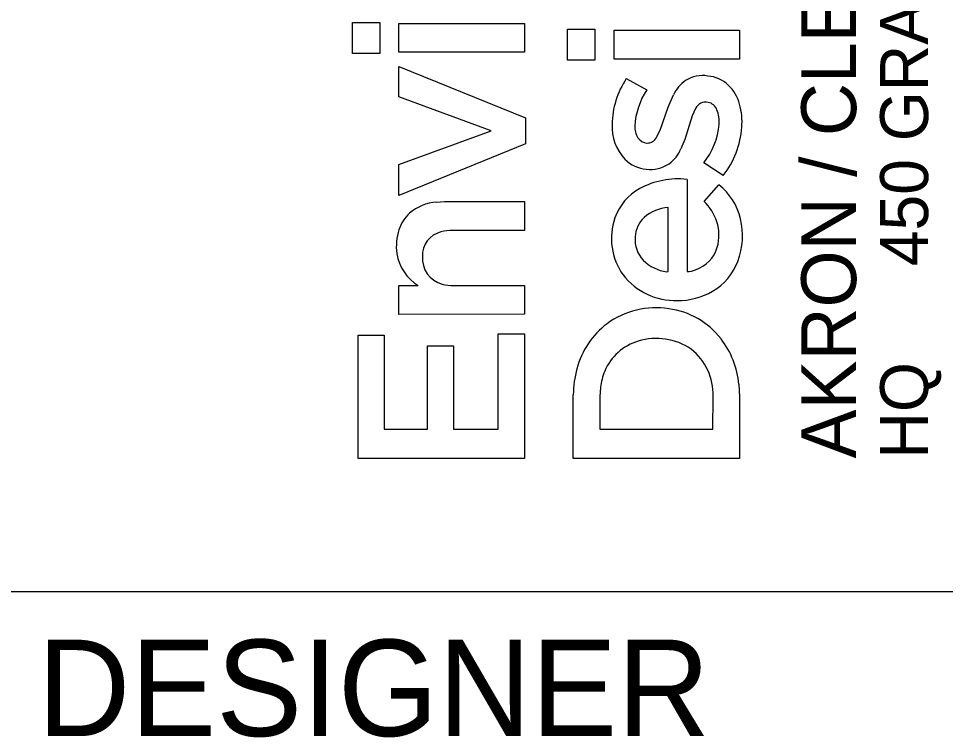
# Model space of a CAD drawing. Extents: x 0 to 34, y 0 to 22.
# Drawn here: x 32.03 to 32.993, y 2.849 to 3.594 of the extents above; entities that cross this region are included whole.
import ezdxf

# ---------------------------------------------------------------- set-up
doc = ezdxf.new("R2010")
doc.units = 0
doc.layers.add('SH_Border', color=7, linetype='Continuous')
doc.layers.add('SH_Data', color=7, linetype='Continuous')

msp = doc.modelspace()

# ---------------------------------------------------------------- linework, layer by layer
at = {"layer": 'SH_Border'}
msp.add_line((32, 3), (33.5, 3), dxfattribs=at)
at = {"layer": 'SH_Data'}
for p, q in [((32.37705, 3.55818), (32.37705, 3.59026)), ((32.37705, 3.59026), (32.40543, 3.59026)), ((32.40543, 3.59026), (32.40543, 3.55818)), ((32.42542, 3.55942), (32.42542, 3.58928)), ((32.42542, 3.58928), (32.55571, 3.58928)), ((32.55571, 3.58928), (32.55571, 3.55942)), ((32.60051, 3.55111), (32.60051, 3.58319)), ((32.60051, 3.58319), (32.62889, 3.58319)), ((32.62889, 3.58319), (32.62889, 3.55111)), ((32.64888, 3.55234), (32.64888, 3.5822)), ((32.64888, 3.5822), (32.77917, 3.5822)), ((32.77917, 3.5822), (32.77917, 3.55234)), ((32.40543, 3.55818), (32.37705, 3.55818)), ((32.55571, 3.55942), (32.42542, 3.55942)), ((32.77917, 3.55234), (32.64888, 3.55234)), ((32.42542, 3.51327), (32.42542, 3.5446)), ((32.42542, 3.5446), (32.5567, 3.4913)), ((32.62889, 3.55111), (32.60051, 3.55111)), ((32.66151, 3.53207), (32.68268, 3.52025)), ((32.52117, 3.47798), (32.42542, 3.51327)), ((32.70483, 3.50258), (32.71036, 3.51526)), ((32.69675, 3.47868), (32.70483, 3.50258)), ((32.73342, 3.50101), (32.72985, 3.4933)), ((32.5567, 3.4913), (32.5567, 3.46441)), ((32.72985, 3.4933), (32.72213, 3.46882)), ((32.42542, 3.44294), (32.52117, 3.47798)), ((32.69299, 3.47117), (32.69675, 3.47868)), ((32.72213, 3.46882), (32.71822, 3.45921)), ((32.5567, 3.46441), (32.42542, 3.41086)), ((32.42542, 3.41086), (32.42542, 3.44294)), ((32.76214, 3.43141), (32.74198, 3.44469)), ((32.72453, 3.42747), (32.72463, 3.33195)), ((32.74228, 3.40465), (32.75768, 3.422)), ((32.46439, 3.40397), (32.47289, 3.40443)), ((32.47289, 3.40443), (32.55571, 3.40443)), ((32.55571, 3.40443), (32.55571, 3.37465)), ((32.70489, 3.33182), (32.70489, 3.39834)), ((32.55571, 3.37465), (32.4814, 3.37457)), ((32.70361, 3.33165), (32.70489, 3.33182)), ((32.42542, 3.31728), (32.44552, 3.31733)), ((32.42542, 3.28747), (32.42542, 3.31728)), ((32.48222, 3.31733), (32.55569, 3.31733)), ((32.55569, 3.31733), (32.55571, 3.28756)), ((32.55571, 3.28756), (32.42542, 3.28747)), ((32.38298, 3.13791), (32.38298, 3.26598)), ((32.38298, 3.26598), (32.41012, 3.26598)), ((32.41012, 3.26598), (32.41012, 3.16827)), ((32.52857, 3.16827), (32.52857, 3.26722)), ((32.52857, 3.26722), (32.55571, 3.26722)), ((32.55571, 3.26722), (32.55571, 3.13791)), ((32.45503, 3.16827), (32.45503, 3.25488)), ((32.45503, 3.25488), (32.48218, 3.25488)), ((32.48218, 3.25488), (32.48218, 3.16827)), ((32.77847, 3.21497), (32.77917, 3.2021)), ((32.63465, 3.21178), (32.63407, 3.2023)), ((32.60643, 3.13799), (32.60644, 3.204)), ((32.63407, 3.2023), (32.63407, 3.16838)), ((32.75149, 3.16834), (32.75153, 3.20239)), ((32.77917, 3.2021), (32.77917, 3.138)), ((32.41012, 3.16827), (32.45503, 3.16827)), ((32.48218, 3.16827), (32.52857, 3.16827)), ((32.63407, 3.16838), (32.75149, 3.16834)), ((32.55571, 3.13791), (32.38298, 3.13791)), ((32.77917, 3.138), (32.60643, 3.13799))]:
    msp.add_line(p, q, dxfattribs=at)
for points in [[(32.37705, 3.55818), (32.37705, 3.59026), (32.40543, 3.59026), (32.40543, 3.55818)], [(32.42542, 3.55942), (32.42542, 3.58928), (32.55571, 3.58928), (32.55571, 3.55942)], [(32.60051, 3.55111), (32.60051, 3.58319), (32.62889, 3.58319), (32.62889, 3.55111)], [(32.64888, 3.55234), (32.64888, 3.5822), (32.77917, 3.5822), (32.77917, 3.55234)], [(32.42542, 3.41086), (32.42542, 3.44294), (32.52117, 3.47798), (32.42542, 3.51327), (32.42542, 3.5446), (32.5567, 3.4913), (32.5567, 3.46441)], [(32.38298, 3.13791), (32.38298, 3.26598), (32.41012, 3.26598), (32.41012, 3.16827), (32.45503, 3.16827), (32.45503, 3.25488), (32.48218, 3.25488), (32.48218, 3.16827), (32.52857, 3.16827), (32.52857, 3.26722), (32.55571, 3.26722), (32.55571, 3.13791)]]:
    msp.add_lwpolyline(points, close=True, dxfattribs=at)
for points in [[(32.66151, 3.53207), (32.68268, 3.52025)], [(32.69299, 3.47117), (32.69675, 3.47868), (32.70483, 3.50258), (32.71036, 3.51526)], [(32.73342, 3.50101), (32.72985, 3.4933), (32.72213, 3.46882), (32.71822, 3.45921)], [(32.76214, 3.43141), (32.74198, 3.44469)], [(32.72453, 3.42747), (32.72463, 3.33195)], [(32.74228, 3.40465), (32.75768, 3.422)], [(32.46439, 3.40397), (32.47289, 3.40443), (32.55571, 3.40443), (32.55571, 3.37465), (32.4814, 3.37457)], [(32.70361, 3.33165), (32.70489, 3.33182), (32.70489, 3.39834)], [(32.42542, 3.28747), (32.42542, 3.31728), (32.44552, 3.31733)], [(32.48222, 3.31733), (32.55569, 3.31733), (32.55571, 3.28756), (32.42542, 3.28747)], [(32.77847, 3.21497), (32.77917, 3.2021), (32.77917, 3.138), (32.60643, 3.13799)], [(32.63465, 3.21178), (32.63407, 3.2023), (32.63407, 3.16838), (32.75149, 3.16834), (32.75153, 3.20239)], [(32.60643, 3.13799), (32.60644, 3.204)]]:
    msp.add_lwpolyline(points, dxfattribs=at)
for centre, radius, start, end in [((32.73636, 3.48258), 0.08973, 146.53104, 178.7571), ((32.73636, 3.48258), 0.08973, 146.53104, 178.7571), ((32.7406, 3.5026), 0.03263, 80.17192, 122.51969), ((32.7406, 3.5026), 0.03263, 80.17192, 122.51969), ((32.74278, 3.49824), 0.03667, 47.79344, 84.68918), ((32.74278, 3.49824), 0.03667, 47.79344, 84.68918), ((32.74661, 3.49713), 0.04053, 125.51182, 153.41595), ((32.74661, 3.49713), 0.04053, 125.51182, 153.41595), ((32.73788, 3.4946), 0.04267, 14.9966, 46.20632), ((32.73788, 3.4946), 0.04267, 14.9966, 46.20632), ((32.74519, 3.4789), 0.07495, 146.51121, 176.91007), ((32.74519, 3.4789), 0.07495, 146.51121, 176.91007), ((32.74384, 3.49631), 0.01143, 76.66094, 155.7053), ((32.74384, 3.49631), 0.01143, 76.66094, 155.7053), ((32.74397, 3.49511), 0.01256, 21.5098, 78.52618), ((32.74397, 3.49511), 0.01256, 21.5098, 78.52618), ((32.71044, 3.48674), 0.07121, 355.83062, 15.39138), ((32.71044, 3.48674), 0.07121, 355.83062, 15.39138), ((32.72592, 3.48766), 0.03209, 354.57264, 22.06805), ((32.72592, 3.48766), 0.03209, 354.57264, 22.06805), ((32.69666, 3.48238), 0.05005, 177.53659, 222.79318), ((32.69666, 3.48238), 0.05005, 177.53659, 222.79318), ((32.68248, 3.49149), 0.0757, 321.81101, 354.79685), ((32.68248, 3.49149), 0.0757, 321.81101, 354.79685), ((32.6931, 3.48233), 0.02276, 178.47474, 211.08679), ((32.6931, 3.48233), 0.02276, 178.47474, 211.08679), ((32.68952, 3.4882), 0.09219, 321.9777, 355.87384), ((32.68952, 3.4882), 0.09219, 321.9777, 355.87384), ((32.68331, 3.4767), 0.01148, 212.23676, 268.37769), ((32.68331, 3.4767), 0.01148, 212.23676, 268.37769), ((32.68342, 3.47589), 0.01067, 267.71603, 333.73375), ((32.68342, 3.47589), 0.01067, 267.71603, 333.73375), ((32.68098, 3.4758), 0.04077, 308.08772, 335.98736), ((32.68098, 3.4758), 0.04077, 308.08772, 335.98736), ((32.68599, 3.47535), 0.0375, 225.98539, 302.47965), ((32.68599, 3.47535), 0.0375, 225.98539, 302.47965), ((32.7152, 3.34414), 0.08384, 83.61499, 118.28755), ((32.7152, 3.34414), 0.08384, 83.61499, 118.28755), ((32.70239, 3.36906), 0.05583, 118.83082, 160.62438), ((32.70239, 3.36906), 0.05583, 118.83082, 160.62438), ((32.71744, 3.37167), 0.06443, 13.53365, 51.36148), ((32.71744, 3.37167), 0.06443, 13.53365, 51.36148), ((32.46871, 3.35428), 0.04988, 94.96958, 130.22249), ((32.46871, 3.35428), 0.04988, 94.96958, 130.22249), ((32.70785, 3.35609), 0.04235, 94.00805, 130.88169), ((32.70785, 3.35609), 0.04235, 94.00805, 130.88169), ((32.70378, 3.36556), 0.05486, 19.03571, 45.44059), ((32.70378, 3.36556), 0.05486, 19.03571, 45.44059), ((32.46348, 3.36263), 0.04015, 132.22192, 161.68183), ((32.46348, 3.36263), 0.04015, 132.22192, 161.68183), ((32.70048, 3.36628), 0.02985, 132.98507, 177.179), ((32.70048, 3.36628), 0.02985, 132.98507, 177.179), ((32.71041, 3.36612), 0.06437, 160.52012, 215.78311), ((32.71041, 3.36612), 0.06437, 160.52012, 215.78311), ((32.71069, 3.3697), 0.047, 344.60586, 17.007), ((32.71069, 3.3697), 0.047, 344.60586, 17.007), ((32.70635, 3.36921), 0.07579, 339.3542, 13.37853), ((32.70635, 3.36921), 0.07579, 339.3542, 13.37853), ((32.47872, 3.35819), 0.05601, 162.27355, 187.79185), ((32.47872, 3.35819), 0.05601, 162.27355, 187.79185), ((32.47482, 3.34867), 0.02498, 103.68646, 182.21874), ((32.47482, 3.34867), 0.02498, 103.68646, 182.21874), ((32.48108, 3.32856), 0.04601, 89.60494, 105.3284), ((32.48108, 3.32856), 0.04601, 89.60494, 105.3284), ((32.7017, 3.36503), 0.03115, 175.00126, 223.28301), ((32.7017, 3.36503), 0.03115, 175.00126, 223.28301), ((32.47026, 3.35802), 0.04762, 188.96199, 238.70369), ((32.47026, 3.35802), 0.04762, 188.96199, 238.70369), ((32.7224, 3.36715), 0.03504, 288.00773, 343.55078), ((32.7224, 3.36715), 0.03504, 288.00773, 343.55078), ((32.47735, 3.34558), 0.02756, 175.58538, 255.14386), ((32.47735, 3.34558), 0.02756, 175.58538, 255.14386), ((32.70891, 3.37363), 0.04231, 225.06188, 262.79738), ((32.70891, 3.37363), 0.04231, 225.06188, 262.79738), ((32.71894, 3.3652), 0.0626, 300.94269, 338.73225), ((32.71894, 3.3652), 0.0626, 300.94269, 338.73225), ((32.72474, 3.35216), 0.02021, 269.7003, 294.8711), ((32.72474, 3.35216), 0.02021, 269.7003, 294.8711), ((32.71253, 3.37054), 0.06872, 217.74516, 271.65431), ((32.71253, 3.37054), 0.06872, 217.74516, 271.65431), ((32.48183, 3.35948), 0.04215, 254.09162, 270.52835), ((32.48183, 3.35948), 0.04215, 254.09162, 270.52835), ((32.71549, 3.37241), 0.07056, 269.20477, 300.33412), ((32.71549, 3.37241), 0.07056, 269.20477, 300.33412), ((32.69229, 3.20792), 0.08641, 81.19402, 125.99844), ((32.69229, 3.20792), 0.08641, 81.19402, 125.99844), ((32.69458, 3.21132), 0.08272, 37.85208, 82.40204), ((32.69458, 3.21132), 0.08272, 37.85208, 82.40204), ((32.69387, 3.20893), 0.08654, 127.23621, 165.14796), ((32.69387, 3.20893), 0.08654, 127.23621, 165.14796), ((32.69279, 3.19862), 0.06389, 55.67272, 107.20935), ((32.69279, 3.19862), 0.06389, 55.67272, 107.20935), ((32.68893, 3.20782), 0.05398, 106.18808, 157.38609), ((32.68893, 3.20782), 0.05398, 106.18808, 157.38609), ((32.68586, 3.20567), 0.09308, 5.73329, 37.30396), ((32.68586, 3.20567), 0.09308, 5.73329, 37.30396), ((32.69291, 3.20499), 0.05867, 357.46616, 52.26647), ((32.69291, 3.20499), 0.05867, 357.46616, 52.26647), ((32.71426, 3.20281), 0.10783, 164.7861, 179.37039), ((32.71426, 3.20281), 0.10783, 164.7861, 179.37039), ((32.69829, 3.20389), 0.06412, 157.35705, 172.92755), ((32.69829, 3.20389), 0.06412, 157.35705, 172.92755)]:
    msp.add_arc(centre, radius, start, end, dxfattribs=at)

# ---------------------------------------------------------------- texts
for s, height, p in [('450 GRANT ST., AKRON, OH  44311', 0.0498462, (32.97489, 3.33738)), ('AKRON / CLEVELAND / COLUMBUS', 0.056969, (32.90012, 3.138)), ('HQ ', 0.049846, (32.97489, 3.138))]:
    msp.add_text(s, height=height, rotation=90, dxfattribs=at).set_placement(p)
msp.add_text('DESIGNER', height=0.1, dxfattribs=at).set_placement((32.05, 2.85))

doc.saveas('drawing.dxf')
